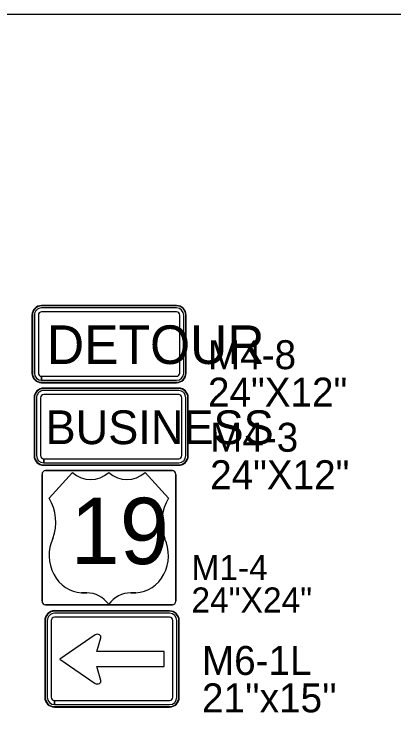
# Model space of a CAD drawing. Extents: x 886234 to 968767, y 455416 to 684046.
# Drawn here: x 961100 to 964172, y 540138 to 545883 of the extents above; entities that cross this region are included whole.
import ezdxf

# ---------------------------------------------------------------- set-up
doc = ezdxf.new("R2010")
doc.units = 0
for name, color, linetype in [('Scratch_Level_3', 7, 'Continuous'), ('TC DEV SIGN BLACK 239', 7, 'Continuous'), ('TC DEV SIGN BLACK ZERO', 7, 'Continuous'), ('TC DEV SIGN ORANGE', 7, 'Continuous'), ('TC DEV SIGN WHITE', 7, 'Continuous')]:
    doc.layers.add(name, color=color, linetype=linetype)

msp = doc.modelspace()

# ---------------------------------------------------------------- linework, layer by layer
at = {"layer": 'Scratch_Level_3'}
msp.add_lwpolyline([(933999.3, 545882.8), (968767.2, 545882.8), (968767.2, 536165.1), (933999.3, 536165.1)], close=True, dxfattribs=at)
at = {"layer": 'TC DEV SIGN BLACK 239'}
for p, q in [((962430.6, 542840.3), (961338.4, 542840.3)), ((962430.6, 542807.8), (961338.4, 542807.8)), ((961279.9, 542781.8), (961279.9, 542313.8)), ((961312.4, 542781.8), (961312.4, 542313.8)), ((962456.6, 542313.8), (962456.6, 542781.8)), ((962489.1, 542313.8), (962489.1, 542781.8)), ((961338.4, 542255.3), (961338.4, 542287.8)), ((961338.8, 542287.8), (962430.6, 542287.8)), ((961338.8, 542287.8), (961338.8, 542255.3)), ((961338.8, 542255.3), (962430.6, 542255.3)), ((962379.4, 542192.4), (961352.3, 542192.4)), ((961571.2, 542178.1), (961571.3, 542178.1)), ((961865.1, 542178.1), (961865.1, 542178.1)), ((961325, 542162.3), (961325, 541137.1)), ((962406.6, 541137.1), (962406.6, 542162.3)), ((962347.9, 541969.5), (962347.9, 541969.5)), ((961413.1, 541645), (961412.4, 541645)), ((962317.8, 541645), (962317.1, 541645)), ((961687, 541204.6), (961645, 541204.8)), ((962085.2, 541204.8), (962043.2, 541204.6)), ((961352.3, 541107), (962379.4, 541107)), ((961865.1, 541111.9), (961865.1, 541111.9)), ((962356.4, 541039.4), (961426.1, 541039.4)), ((961366.8, 540980.1), (961366.8, 540359.9)), ((961399.8, 540980.1), (961399.7, 540359.9)), ((962356.4, 541006.4), (961426.1, 541006.4)), ((962382.7, 540359.9), (962382.7, 540980.1)), ((962415.7, 540359.9), (962415.7, 540980.1)), ((961755.4, 540865.6), (961469.5, 540668.7)), ((961767.8, 540729.4), (961800.1, 540841.7)), ((962313.6, 540729.4), (961767.8, 540729.4)), ((962313.6, 540610), (962313.6, 540729.4)), ((961469.5, 540668.7), (961755.4, 540471.7)), ((961800.1, 540495.7), (961767.9, 540610)), ((961767.9, 540610), (962313.6, 540610)), ((961426.1, 540300.5), (961426.1, 540333.5)), ((961426.4, 540333.5), (962356.3, 540333.5)), ((961426.4, 540333.5), (961426.4, 540300.5)), ((961426.4, 540300.5), (962356.3, 540300.5))]:
    msp.add_line(p, q, dxfattribs=at)
for points in [[(961352.3, 542192.4), (962379.4, 542192.4)], [(961382.3, 541969.5), (961382.3, 541969.5), (961571.2, 542178.1)], [(962159, 542178.1), (962159, 542178.1), (962347.9, 541969.5)], [(961325, 541137.1), (961325, 542162.3)], [(962406.6, 542162.3), (962406.6, 541137.1)], [(962379.4, 541107), (961352.3, 541107)]]:
    msp.add_lwpolyline(points, dxfattribs=at)
for centre, major_axis, ratio, start_param, end_param in [((961338.4, 542781.8), (58.5, 0), 0.999865, 1.570796, 3.141593), ((961338.4, 542781.8), (26, 0), 0.999865, 1.570796, 3.141593), ((962430.6, 542781.8), (58.5, 0), 0.999865, 0, 1.570796), ((962430.6, 542781.8), (26, 0), 0.999865, 0, 1.570796), ((961338.4, 542313.8), (58.5, 0), 0.999865, 3.141593, 4.712389), ((961338.4, 542313.8), (26, 0), 0.999865, 3.141593, 4.712389), ((962430.6, 542313.8), (58.5, 0), 0.999865, 4.712389, 6.283185), ((962430.6, 542313.8), (26, 0), 0.999865, 4.712389, 6.283185), ((961352.3, 542162.3), (0, -30.1), 0.905624, 3.141593, 4.712389), ((961352.3, 542162.3), (0, -30.1), 0.905624, 3.141593, 4.712389), ((961718.2, 542374.8), (0, -255), 0.905624, 5.593452, 6.972919), ((962012, 542374.8), (0, -255), 0.905624, 5.593452, 6.972919), ((962379.4, 542162.3), (0, 30.1), 0.905624, 4.712389, 6.283185), ((962379.4, 542162.3), (0, 30.1), 0.905624, 4.712389, 6.283185), ((961120.8, 541775.9), (0, -347.7), 0.905624, 1.184601, 2.161129), ((962609.5, 541775.9), (0, -347.7), 0.905624, 4.122057, 5.098584), ((961655.2, 541505.9), (0, 301.3), 0.905624, 1.091068, 3.104197), ((962075, 541505.9), (0, 301.3), 0.905624, 3.178989, 5.192118), ((961687, 540949.7), (0, 255), 0.905624, 5.402164, 6.283185), ((962043.2, 540949.7), (0, -255), 0.905624, 3.141593, 4.022614), ((961352.3, 541137.1), (0, -30.1), 0.905624, 4.712389, 6.283185), ((961352.3, 541137.1), (0, -30.1), 0.905624, 4.712389, 6.283185), ((962379.4, 541137.1), (0, 30.1), 0.905624, 3.141593, 4.712389), ((962379.4, 541137.1), (0, 30.1), 0.905624, 3.141593, 4.712389), ((961426.1, 540980.1), (59.3, 0), 0.999865, 1.570796, 3.141593), ((962356.4, 540980.1), (59.3, 0), 0.999865, 0, 1.570796), ((961426.1, 540980.1), (26.4, 0), 0.999865, 1.570796, 3.141593), ((962356.4, 540980.1), (26.4, 0), 0.999865, 0, 1.570796), ((961772.1, 540848.1), (-29.4, 0), 0.720018, 2.830616, 5.313575), ((961772.1, 540489.2), (-29.4, 0), 0.720018, 0.969609, 3.452568), ((961426.1, 540359.9), (59.3, 0), 0.999865, 3.141593, 4.712389), ((961426.1, 540359.9), (26.4, 0), 0.999865, 3.141593, 4.712389), ((962356.3, 540359.9), (59.3, 0), 0.999865, 4.712389, 6.283185), ((962356.3, 540359.9), (26.4, 0), 0.999865, 4.712389, 6.283185)]:
    msp.add_ellipse(centre, major_axis=major_axis, ratio=ratio, start_param=start_param, end_param=end_param, dxfattribs=at)
at = {"layer": 'TC DEV SIGN BLACK ZERO'}
for p, q in [((962413.3, 543527.5), (961321.2, 543527.5)), ((961321.2, 543524.3), (961321.2, 543524.3)), ((962413.3, 543524.2), (961321.2, 543524.3)), ((962413.3, 543508), (961321.2, 543508)), ((962413.3, 543524.2), (962413.3, 543524.3)), ((961243.1, 543449.5), (961243.1, 542981.5)), ((961246.4, 543449.5), (961246.4, 542981.5)), ((961246.4, 543449.5), (961246.4, 543449.5)), ((961262.6, 543449.5), (961262.6, 542981.5)), ((961295.2, 543449.5), (961295.2, 542981.5)), ((962413.3, 543475.5), (961321.2, 543475.5)), ((962439.3, 542981.5), (962439.3, 543449.5)), ((962471.8, 542981.5), (962471.8, 543449.5)), ((962488.1, 543449.5), (962488.1, 543449.5)), ((962488.1, 542981.5), (962488.1, 543449.5)), ((962491.3, 542981.5), (962491.3, 543449.5)), ((961246.4, 542981.5), (961246.4, 542981.5)), ((962488.1, 542981.5), (962488.1, 542981.5)), ((961321.2, 542923), (961321.2, 542955.5)), ((961321.5, 542955.5), (962413.3, 542955.5)), ((961321.5, 542955.5), (961321.5, 542923)), ((961321.5, 542923), (962413.3, 542923)), ((961321.2, 542903.5), (961321.2, 542906.8)), ((961321.2, 542906.8), (961321.2, 542906.8)), ((961321.2, 542906.8), (962413.3, 542906.8)), ((961321.2, 542906.8), (961321.2, 542903.5)), ((961321.2, 542903.5), (962413.3, 542903.5)), ((962413.3, 542906.8), (962413.3, 542906.8)), ((962430.6, 542859.8), (961338.4, 542859.8)), ((961338.4, 542856.6), (961338.4, 542856.6)), ((962430.6, 542856.5), (961338.4, 542856.6)), ((962430.6, 542856.5), (962430.6, 542856.6)), ((961260.4, 542781.8), (961260.4, 542313.8)), ((961263.7, 542781.8), (961263.7, 542313.8)), ((961263.7, 542781.8), (961263.7, 542781.8)), ((962505.4, 542781.8), (962505.4, 542781.8)), ((962505.4, 542313.8), (962505.4, 542781.8)), ((962508.6, 542313.8), (962508.6, 542781.8)), ((961263.7, 542313.8), (961263.7, 542313.8)), ((962505.4, 542313.8), (962505.4, 542313.8)), ((961338.4, 542235.8), (961338.4, 542239.1)), ((961338.4, 542239.1), (961338.4, 542239.1)), ((961338.5, 542239.1), (962430.6, 542239.1)), ((961338.5, 542239.1), (961338.5, 542235.8)), ((961338.5, 542235.8), (962430.6, 542235.8)), ((962430.6, 542239.1), (962430.6, 542239.1)), ((962356.4, 541059.2), (961426.1, 541059.2)), ((961426.1, 541055.9), (961426.1, 541055.9)), ((962356.4, 541055.9), (961426.1, 541055.9)), ((962356.4, 541055.9), (962356.4, 541055.9)), ((961347, 540980.1), (961347, 540359.9)), ((961350.3, 540980.1), (961350.3, 540359.9)), ((961350.3, 540980.1), (961350.3, 540980.1)), ((962432.2, 540980.1), (962432.2, 540980.1)), ((962432.2, 540359.9), (962432.2, 540980.1)), ((962435.4, 540359.9), (962435.5, 540980.1)), ((961350.3, 540359.9), (961350.3, 540359.9)), ((962432.2, 540359.9), (962432.1, 540359.9)), ((961426.1, 540280.8), (961426.1, 540284.1)), ((961426.1, 540284.1), (961426.1, 540284.1)), ((961426.2, 540284.1), (962356.3, 540284.1)), ((961426.2, 540284.1), (961426.2, 540280.8)), ((961426.2, 540280.8), (962356.3, 540280.8)), ((962356.3, 540284.1), (962356.3, 540284.1))]:
    msp.add_line(p, q, dxfattribs=at)
for centre, major_axis, start_param, end_param in [((961321.2, 543449.5), (78, 0), 1.570796, 3.141593), ((961321.2, 543449.5), (74.8, 0), 1.570796, 3.141593), ((961321.2, 543449.5), (58.5, 0), 1.570796, 3.141593), ((962413.3, 543449.5), (78, 0), 0, 1.570796), ((962413.3, 543449.5), (74.8, 0), 0, 1.570796), ((962413.3, 543449.5), (58.5, 0), 0, 1.570796), ((961321.2, 543449.5), (26, 0), 1.570796, 3.141593), ((962413.3, 543449.5), (26, 0), 0, 1.570796), ((961321.2, 542981.5), (78, 0), 3.141593, 4.712389), ((961321.2, 542981.5), (74.8, 0), 3.141593, 4.712389), ((961321.2, 542981.5), (58.5, 0), 3.141593, 4.712389), ((961321.2, 542981.5), (26, 0), 3.141593, 4.712389), ((962413.3, 542981.5), (58.5, 0), 4.712389, 6.283185), ((962413.3, 542981.5), (26, 0), 4.712389, 6.283185), ((962413.3, 542981.5), (78, 0), 4.712389, 6.283185), ((962413.3, 542981.5), (74.8, 0), 4.712389, 6.283185), ((961338.4, 542781.8), (78, 0), 1.570796, 3.141593), ((961338.4, 542781.8), (74.8, 0), 1.570796, 3.141593), ((962430.6, 542781.8), (78, 0), 0, 1.570796), ((962430.6, 542781.8), (74.8, 0), 0, 1.570796), ((961338.4, 542313.8), (78, 0), 3.141593, 4.712389), ((961338.4, 542313.8), (74.8, 0), 3.141593, 4.712389), ((962430.6, 542313.8), (78, 0), 4.712389, 6.283185), ((962430.6, 542313.8), (74.8, 0), 4.712389, 6.283185), ((961426.1, 540980.1), (79.1, 0), 1.570796, 3.141593), ((961426.1, 540980.1), (75.8, 0), 1.570796, 3.141593), ((962356.4, 540980.1), (79.1, 0), 0, 1.570796), ((962356.4, 540980.1), (75.8, 0), 0, 1.570796), ((961426.1, 540359.9), (79.1, 0), 3.141593, 4.712389), ((961426.1, 540359.9), (75.8, 0), 3.141593, 4.712389), ((962356.3, 540359.9), (79.1, 0), 4.712389, 6.283185), ((962356.3, 540359.9), (75.8, 0), 4.712389, 6.283185)]:
    msp.add_ellipse(centre, major_axis=major_axis, ratio=0.999865, start_param=start_param, end_param=end_param, dxfattribs=at)
at = {"layer": 'TC DEV SIGN ORANGE'}
for p, q in [((962413.3, 543527.5), (961321.2, 543527.5)), ((961243.1, 543449.5), (961243.1, 542981.5)), ((962491.3, 542981.5), (962491.3, 543449.5)), ((961321.2, 542903.5), (962413.3, 542903.5))]:
    msp.add_line(p, q, dxfattribs=at)
for centre, start_param, end_param in [((961321.2, 543449.5), 1.570796, 3.141593), ((962413.3, 543449.5), 0, 1.570796), ((961321.2, 542981.5), 3.141593, 4.712389), ((962413.3, 542981.5), 4.712389, 6.283185)]:
    msp.add_ellipse(centre, major_axis=(78, 0), ratio=0.999865, start_param=start_param, end_param=end_param, dxfattribs=at)
at = {"layer": 'TC DEV SIGN WHITE'}
for p, q in [((962430.6, 542859.8), (961338.4, 542859.8)), ((961260.4, 542781.8), (961260.4, 542313.8)), ((962508.6, 542313.8), (962508.6, 542781.8)), ((961338.4, 542235.8), (962430.6, 542235.8)), ((961382.3, 541969.5), (961571.2, 542178.1)), ((961571.3, 542178.1), (961382.3, 541969.5)), ((962159, 542178.1), (962347.9, 541969.5)), ((962347.9, 541969.5), (962159, 542178.1)), ((961412.4, 541645), (961413.1, 541645)), ((961645, 541204.8), (961687, 541204.6)), ((962043.2, 541204.6), (962085.2, 541204.8)), ((961865.1, 541111.9), (961865.1, 541111.9)), ((962356.4, 541059.2), (961426.1, 541059.2)), ((961347, 540980.1), (961347, 540359.9)), ((962435.4, 540359.9), (962435.5, 540980.1)), ((961426.1, 540280.8), (962356.3, 540280.8))]:
    msp.add_line(p, q, dxfattribs=at)
for points in [[(961865.1, 542178.1), (961865.1, 542178.1)], [(962317.1, 541645), (962317.8, 541645)]]:
    msp.add_lwpolyline(points, dxfattribs=at)
for centre, major_axis, ratio, start_param, end_param in [((961338.4, 542781.8), (78, 0), 0.999865, 1.570796, 3.141593), ((962430.6, 542781.8), (78, 0), 0.999865, 0, 1.570796), ((961338.4, 542313.8), (78, 0), 0.999865, 3.141593, 4.712389), ((962430.6, 542313.8), (78, 0), 0.999865, 4.712389, 6.283185), ((961718.2, 542374.8), (0, -255), 0.905624, 5.593452, 6.972919), ((961718.2, 542374.8), (0, -255), 0.905624, 5.593452, 6.972919), ((962012, 542374.8), (0, -255), 0.905624, 5.593452, 6.972919), ((962012, 542374.8), (0, -255), 0.905624, 5.593452, 6.972919), ((961120.8, 541775.9), (0, -347.7), 0.905624, 1.184601, 2.161129), ((961120.8, 541775.9), (0, -347.7), 0.905624, 1.184601, 2.161129), ((962609.5, 541775.9), (0, -347.7), 0.905624, 4.122057, 5.098584), ((962609.5, 541775.9), (0, -347.7), 0.905624, 4.122057, 5.098584), ((961655.2, 541505.9), (0, 301.3), 0.905624, 1.091068, 3.104197), ((961655.2, 541505.9), (0, 301.3), 0.905624, 1.091068, 3.104197), ((962075, 541505.9), (0, 301.3), 0.905624, 3.178989, 5.192118), ((962075, 541505.9), (0, 301.3), 0.905624, 3.178989, 5.192118), ((961687, 540949.7), (0, 255), 0.905624, 5.402164, 6.283185), ((961687, 540949.7), (0, 255), 0.905624, 5.402164, 6.283185), ((962043.2, 540949.7), (0, -255), 0.905624, 3.141593, 4.022614), ((962043.2, 540949.7), (0, -255), 0.905624, 3.141593, 4.022614), ((961426.1, 540980.1), (79.1, 0), 0.999865, 1.570796, 3.141593), ((962356.4, 540980.1), (79.1, 0), 0.999865, 0, 1.570796), ((961426.1, 540359.9), (79.1, 0), 0.999865, 3.141593, 4.712389), ((962356.3, 540359.9), (79.1, 0), 0.999865, 4.712389, 6.283185)]:
    msp.add_ellipse(centre, major_axis=major_axis, ratio=ratio, start_param=start_param, end_param=end_param, dxfattribs=at)

# ---------------------------------------------------------------- texts
at = {"layer": 'TC DEV SIGN BLACK 239'}
for s, height, p in [('BUSINESS', 273, (961353.5, 542406.6)), ('19', 536.04, (961555.3, 541436.9))]:
    msp.add_text(s, height=height, rotation=360, dxfattribs=at).set_placement(p)
at = {"layer": 'TC DEV SIGN BLACK ZERO'}
for s, height, p in [('DETOUR', 312, (961364.5, 543054.8)), ('M4-8', 234, (962667.9, 543012.8)), ('24"X12"', 234, (962667.9, 542710.2)), ('M4-3', 234, (962685.2, 542345.1)), ('24"X12"', 234, (962685.2, 542042.5)), ('M1-4', 202.8, (962533.9, 541307.5)), ('24"X24"', 202.8, (962533.9, 541045.2)), ('M6-1L', 234, (962619, 540540.7)), ("21''x15''", 234, (962619, 540238.1))]:
    msp.add_text(s, height=height, rotation=360, dxfattribs=at).set_placement(p)

doc.saveas('drawing.dxf')
